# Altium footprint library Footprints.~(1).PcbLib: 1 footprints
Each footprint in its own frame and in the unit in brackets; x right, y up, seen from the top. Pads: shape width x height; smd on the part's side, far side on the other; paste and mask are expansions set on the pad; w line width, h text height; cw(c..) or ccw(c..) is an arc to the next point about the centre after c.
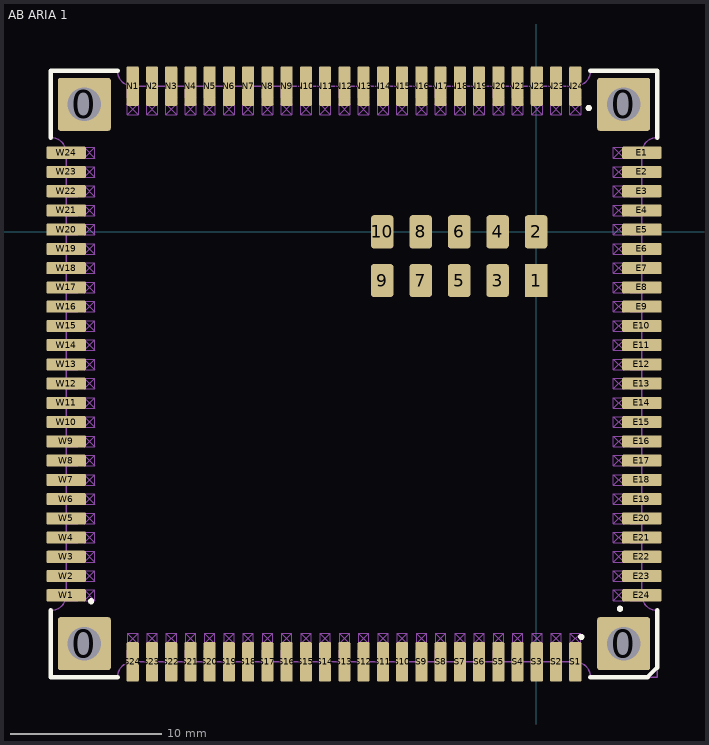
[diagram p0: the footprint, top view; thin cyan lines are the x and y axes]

## AB ARIA 1 [mm]
pads (110):
  rrect10% 3.5x3.5 hole 2.2 mask+0.2: 0(-29.82,-27.18) 0(-29.82,8.42) 0(5.78,-27.18) 0(5.78,8.42)
  rect 1.5x2.2 smd paste-0.1: 1(0,-3.21)
  rrect30% 1.5x2.2 smd paste-0.1: 2(0,0) 3(-2.54,-3.21) 4(-2.54,0) 5(-5.08,-3.21) 6(-5.08,0) 7(-7.62,-3.21) 8(-7.62,0) 9(-10.16,-3.21) 10(-10.16,0)
  rrect20% 2.6x0.8 smd paste+0.05: E1(6.98,5.225) E2(6.98,3.955) E3(6.98,2.685) E4(6.98,1.415) E5(6.98,0.145) E6(6.98,-1.125) E7(6.98,-2.395) E8(6.98,-3.665) E9(6.98,-4.935) E10(6.98,-6.205) E11(6.98,-7.475) E12(6.98,-8.745) E13(6.98,-10.015) E14(6.98,-11.285) E15(6.98,-12.555) E16(6.98,-13.825) E17(6.98,-15.095) E18(6.98,-16.365) E19(6.98,-17.635) E20(6.98,-18.905) E21(6.98,-20.175) E22(6.98,-21.445) E23(6.98,-22.715) E24(6.98,-23.985) W1(-31.02,-23.985) W2(-31.02,-22.715) W3(-31.02,-21.445) W4(-31.02,-20.175) W5(-31.02,-18.905) W6(-31.02,-17.635) W7(-31.02,-16.365) W8(-31.02,-15.095) W9(-31.02,-13.825) W10(-31.02,-12.555) W11(-31.02,-11.285) W12(-31.02,-10.015) W13(-31.02,-8.745) W14(-31.02,-7.475) W15(-31.02,-6.205) W16(-31.02,-4.935) W17(-31.02,-3.665) W18(-31.02,-2.395) W19(-31.02,-1.125) W20(-31.02,0.145) W21(-31.02,1.415) W22(-31.02,2.685) W23(-31.02,3.955) W24(-31.02,5.225)
  rrect20% 0.8x2.6 smd paste+0.05: N1(-26.625,9.62) N2(-25.355,9.62) N3(-24.085,9.62) N4(-22.815,9.62) N5(-21.545,9.62) N6(-20.275,9.62) N7(-19.005,9.62) N8(-17.735,9.62) N9(-16.465,9.62) N10(-15.195,9.62) N11(-13.925,9.62) N12(-12.655,9.62) N13(-11.385,9.62) N14(-10.115,9.62) N15(-8.845,9.62) N16(-7.575,9.62) N17(-6.305,9.62) N18(-5.035,9.62) N19(-3.765,9.62) N20(-2.495,9.62) N21(-1.225,9.62) N22(0.045,9.62) N23(1.315,9.62) N24(2.585,9.62) S1(2.585,-28.38) S2(1.315,-28.38) S3(0.045,-28.38) S4(-1.225,-28.38) S5(-2.495,-28.38) S6(-3.765,-28.38) S7(-5.035,-28.38) S8(-6.305,-28.38) S9(-7.575,-28.38) S10(-8.845,-28.38) S11(-10.115,-28.38) S12(-11.385,-28.38) S13(-12.655,-28.38) S14(-13.925,-28.38) S15(-15.195,-28.38) S16(-16.465,-28.38) S17(-17.735,-28.38) S18(-19.005,-28.38) S19(-20.275,-28.38) S20(-21.545,-28.38) S21(-22.815,-28.38) S22(-24.085,-28.38) S23(-25.355,-28.38) S24(-26.625,-28.38)
Top Overlay:
  circle w0.254: c2.98,-26.73 r0.075
  circle w0.254: c-29.37,-24.38 r0.075
  circle w0.254: c3.472,8.174 r0.075
  circle w0.254: c5.534,-24.872 r0.075
  lines w0.3: -32.02,-24.985 -32.02,-29.38 ; -32.02,6.225 -32.02,10.62 -27.625,10.62 ; -27.625,-29.38 -32.02,-29.38 ; 3.585,-29.38 7.355,-29.38 7.98,-28.755 7.98,-24.985 ; 3.585,10.62 7.98,10.62 ; 7.98,6.225 7.98,10.62 ; -32.02,-29.38 -32.02,-29.38 ; -27.625,10.62 -27.625,10.62 ; 7.98,10.62 7.98,10.62
Top Paste:
  lines w0.8: -32.77,-23.99 -32.47,-23.99 ; -32.77,-22.72 -32.47,-22.72 ; -32.77,-21.45 -32.47,-21.45 ; -32.77,-20.18 -32.47,-20.18 ; -32.77,-18.91 -32.47,-18.91 ; -32.77,-17.64 -32.47,-17.64 ; -32.77,-16.37 -32.47,-16.37 ; -32.77,-15.1 -32.47,-15.1 ; -32.77,-13.83 -32.47,-13.83 ; -32.77,-12.56 -32.47,-12.56 ; -32.77,-11.29 -32.47,-11.29 ; -32.77,-10.02 -32.47,-10.02 ; -32.77,-8.75 -32.47,-8.75 ; -32.77,-7.48 -32.47,-7.48 ; -32.77,-6.21 -32.47,-6.21 ; -32.77,-4.94 -32.47,-4.94 ; -32.77,-3.67 -32.47,-3.67 ; -32.77,-2.4 -32.47,-2.4 ; -32.77,-1.13 -32.47,-1.13 ; -32.77,0.14 -32.47,0.14 ; -32.77,1.41 -32.47,1.41 ; -32.77,2.68 -32.47,2.68 ; -32.77,3.95 -32.47,3.95 ; -32.77,5.22 -32.47,5.22 ; -26.63,11.07 -26.63,11.37 ; -26.62,-30.13 -26.62,-29.83 ; -25.36,11.07 -25.36,11.37 ; -25.35,-30.13 -25.35,-29.83 ; -24.09,11.07 -24.09,11.37 ; -24.08,-30.13 -24.08,-29.83 ; -22.82,11.07 -22.82,11.37 ; -22.81,-30.13 -22.81,-29.83 ; -21.55,11.07 -21.55,11.37 ; -21.54,-30.13 -21.54,-29.83 ; -20.28,11.07 -20.28,11.37 ; -20.27,-30.13 -20.27,-29.83 ; -19.01,11.07 -19.01,11.37 ; -19,-30.13 -19,-29.83 ; -17.74,11.07 -17.74,11.37 ; -17.73,-30.13 -17.73,-29.83 ; -16.47,11.07 -16.47,11.37 ; -16.46,-30.13 -16.46,-29.83 ; -15.2,11.07 -15.2,11.37 ; -15.19,-30.13 -15.19,-29.83 ; -13.93,11.07 -13.93,11.37 ; -13.92,-30.13 -13.92,-29.83 ; -12.66,11.07 -12.66,11.37 ; -12.65,-30.13 -12.65,-29.83 ; -11.39,11.07 -11.39,11.37 ; -11.38,-30.13 -11.38,-29.83 ; -10.12,11.07 -10.12,11.37 ; -10.11,-30.13 -10.11,-29.83 ; -8.85,11.07 -8.85,11.37 ; -8.84,-30.13 -8.84,-29.83 ; -7.58,11.07 -7.58,11.37 ; -7.57,-30.13 -7.57,-29.83 ; -6.31,11.07 -6.31,11.37 ; -6.3,-30.13 -6.3,-29.83 ; -5.04,11.07 -5.04,11.37 ; -5.03,-30.13 -5.03,-29.83 ; -3.77,11.07 -3.77,11.37 ; -3.76,-30.13 -3.76,-29.83 ; -2.5,11.07 -2.5,11.37 ; -2.49,-30.13 -2.49,-29.83 ; -1.23,11.07 -1.23,11.37 ; -1.22,-30.13 -1.22,-29.83 ; 0.04,11.07 0.04,11.37 ; 0.05,-30.13 0.05,-29.83 ; 1.31,11.07 1.31,11.37 ; 1.32,-30.13 1.32,-29.83 ; 2.58,11.07 2.58,11.37 ; 2.59,-30.13 2.59,-29.83 ; 8.43,-23.98 8.73,-23.98 ; 8.43,-22.71 8.73,-22.71 ; 8.43,-21.44 8.73,-21.44 ; 8.43,-20.17 8.73,-20.17 ; 8.43,-18.9 8.73,-18.9 ; 8.43,-17.63 8.73,-17.63 ; 8.43,-16.36 8.73,-16.36 ; 8.43,-15.09 8.73,-15.09 ; 8.43,-13.82 8.73,-13.82 ; 8.43,-12.55 8.73,-12.55 ; 8.43,-11.28 8.73,-11.28 ; 8.43,-10.01 8.73,-10.01 ; 8.43,-8.74 8.73,-8.74 ; 8.43,-7.47 8.73,-7.47 ; 8.43,-6.2 8.73,-6.2 ; 8.43,-4.93 8.73,-4.93 ; 8.43,-3.66 8.73,-3.66 ; 8.43,-2.39 8.73,-2.39 ; 8.43,-1.12 8.73,-1.12 ; 8.43,0.15 8.73,0.15 ; 8.43,1.42 8.73,1.42 ; 8.43,2.69 8.73,2.69 ; 8.43,3.96 8.73,3.96 ; 8.43,5.23 8.73,5.23
Bottom Solder:
  region: -1.866,-2.181 -3.23,-2.181 -3.23,-4.219 -1.866,-4.219
  region: -1.857,1.017 -3.221,1.017 -3.221,-1.021 -1.857,-1.021
  region: 0.68,1.017 -0.684,1.017 -0.684,-1.021 0.68,-1.021
Mechanical 13:
  lines w0.1: 2.585,-28.38 cw(c2.585,-29.38) 3.585,-29.38 7.98,-29.38 7.98,-24.985 cw(c7.98,-23.985) 6.98,-23.985 6.98,5.225 cw(c7.98,5.225) 7.98,6.225 7.98,10.62 3.585,10.62 cw(c2.585,10.62) 2.585,9.62 -26.625,9.62 cw(c-26.625,10.62) -27.625,10.62 -32.02,10.62 -32.02,6.225 cw(c-32.02,5.225) -31.02,5.225 -31.02,-23.985 cw(c-32.02,-23.985) -32.02,-24.985 -32.02,-29.38 -27.625,-29.38 cw(c-26.625,-29.38) -26.625,-28.38 2.635,-28.38
Mechanical 15:
  drawing of 1308 lines, arcs and shapes, not listed
3D body: height 2.75, standoff 0.01, extent -32.075,-29.435 8.034,10.674
3D body: height 0.1, standoff 0.01, extent -10.81,-4.21 -9.51,-2.21
3D body: height 0.1, standoff 0.01, extent -8.27,-4.21 -6.97,-2.21
3D body: height 0.1, standoff 0.01, extent -5.73,-4.21 -4.43,-2.21
3D body: height 0.1, standoff 0.01, extent -3.19,-4.21 -1.89,-2.21
3D body: height 0.1, standoff 0.01, extent -0.65,-4.21 0.65,-2.21
3D body: height 0.1, standoff 0.01, extent -10.81,-1 -9.51,1
3D body: height 0.1, standoff 0.01, extent -8.27,-1 -6.97,1
3D body: height 0.1, standoff 0.01, extent -5.73,-1 -4.43,1
3D body: height 0.1, standoff 0.01, extent -3.19,-1 -1.89,1
3D body: height 0.1, standoff 0.01, extent -0.65,-1 0.65,1
3D body: height 1.51, standoff 0.01, extent -12.66,4.32 -11.3,5.89
3D body: height 1.51, standoff 0.01, extent -13.619,6.619 -10.42,8.22
3D body: height 1.51, standoff 1.4, extent 5.8,4.875 7.03,5.575
3D body: height 0.1, standoff 0.01, extent 5.1,4.875 5.8,5.575
3D body: height 1.4, standoff 0.01, extent 6.21,4.875 7.03,5.575
3D body: height 1.4, standoff 0.01, extent 6.21,3.605 7.03,4.305
3D body: height 0.1, standoff 0.01, extent 5.1,3.605 5.8,4.305
3D body: height 1.51, standoff 1.4, extent 6.21,3.605 7.03,4.305
3D body: height 1.4, standoff 0.01, extent 6.21,2.335 7.03,3.035
3D body: height 0.1, standoff 0.01, extent 5.1,2.335 5.8,3.035
3D body: height 1.51, standoff 1.4, extent 6.21,2.335 7.03,3.035
3D body: height 1.4, standoff 0.01, extent 6.21,1.065 7.03,1.765
3D body: height 0.1, standoff 0.01, extent 5.1,1.065 5.8,1.765
3D body: height 1.51, standoff 1.4, extent 6.21,1.065 7.03,1.765
3D body: height 1.4, standoff 0.01, extent 6.21,-0.205 7.03,0.495
3D body: height 0.1, standoff 0.01, extent 5.1,-0.205 5.8,0.495
3D body: height 1.51, standoff 1.4, extent 6.21,-0.205 7.03,0.495
3D body: height 1.4, standoff 0.01, extent 6.21,-1.475 7.03,-0.775
3D body: height 0.1, standoff 0.01, extent 5.1,-1.475 5.8,-0.775
3D body: height 1.51, standoff 1.4, extent 6.21,-1.475 7.03,-0.775
3D body: height 1.4, standoff 0.01, extent 6.21,-2.745 7.03,-2.045
3D body: height 0.1, standoff 0.01, extent 5.1,-2.745 5.8,-2.045
3D body: height 1.51, standoff 1.4, extent 6.21,-2.745 7.03,-2.045
3D body: height 1.4, standoff 0.01, extent 6.21,-4.015 7.03,-3.315
3D body: height 0.1, standoff 0.01, extent 5.1,-4.015 5.8,-3.315
3D body: height 1.51, standoff 1.4, extent 6.21,-4.015 7.03,-3.315
3D body: height 1.4, standoff 0.01, extent 6.21,-5.285 7.03,-4.585
3D body: height 0.1, standoff 0.01, extent 5.1,-5.285 5.8,-4.585
3D body: height 1.51, standoff 1.4, extent 6.21,-5.285 7.03,-4.585
3D body: height 1.4, standoff 0.01, extent 6.21,-6.555 7.03,-5.855
3D body: height 0.1, standoff 0.01, extent 5.1,-6.555 5.8,-5.855
3D body: height 1.51, standoff 1.4, extent 6.21,-6.555 7.03,-5.855
3D body: height 1.4, standoff 0.01, extent 6.21,-7.825 7.03,-7.125
3D body: height 0.1, standoff 0.01, extent 5.1,-7.825 5.8,-7.125
3D body: height 1.51, standoff 1.4, extent 6.21,-7.825 7.03,-7.125
3D body: height 1.4, standoff 0.01, extent 6.21,-9.095 7.03,-8.395
3D body: height 0.1, standoff 0.01, extent 5.1,-9.095 5.8,-8.395
3D body: height 1.51, standoff 1.4, extent 6.21,-9.095 7.03,-8.395
3D body: height 1.4, standoff 0.01, extent 6.21,-10.365 7.03,-9.665
3D body: height 0.1, standoff 0.01, extent 5.1,-10.365 5.8,-9.665
3D body: height 1.51, standoff 1.4, extent 6.21,-10.365 7.03,-9.665
3D body: height 1.4, standoff 0.01, extent 6.21,-11.635 7.03,-10.935
3D body: height 0.1, standoff 0.01, extent 5.1,-11.635 5.8,-10.935
3D body: height 1.51, standoff 1.4, extent 6.21,-11.635 7.03,-10.935
3D body: height 1.4, standoff 0.01, extent 6.21,-12.905 7.03,-12.205
3D body: height 0.1, standoff 0.01, extent 5.1,-12.905 5.8,-12.205
3D body: height 1.51, standoff 1.4, extent 6.21,-12.905 7.03,-12.205
3D body: height 1.4, standoff 0.01, extent 6.21,-14.175 7.03,-13.475
3D body: height 0.1, standoff 0.01, extent 5.1,-14.175 5.8,-13.475
3D body: height 1.51, standoff 1.4, extent 6.21,-14.175 7.03,-13.475
3D body: height 1.4, standoff 0.01, extent 6.21,-15.445 7.03,-14.745
3D body: height 0.1, standoff 0.01, extent 5.1,-15.445 5.8,-14.745
3D body: height 1.51, standoff 1.4, extent 6.21,-15.445 7.03,-14.745
3D body: height 1.4, standoff 0.01, extent 6.21,-16.715 7.03,-16.015
3D body: height 0.1, standoff 0.01, extent 5.1,-16.715 5.8,-16.015
3D body: height 1.51, standoff 1.4, extent 6.21,-16.715 7.03,-16.015
3D body: height 1.4, standoff 0.01, extent 6.21,-17.985 7.03,-17.285
3D body: height 0.1, standoff 0.01, extent 5.1,-17.985 5.8,-17.285
3D body: height 1.51, standoff 1.4, extent 6.21,-17.985 7.03,-17.285
3D body: height 1.4, standoff 0.01, extent 6.21,-19.255 7.03,-18.555
3D body: height 0.1, standoff 0.01, extent 5.1,-19.255 5.8,-18.555
3D body: height 1.51, standoff 1.4, extent 6.21,-19.255 7.03,-18.555
3D body: height 1.4, standoff 0.01, extent 6.21,-20.525 7.03,-19.825
3D body: height 0.1, standoff 0.01, extent 5.1,-20.525 5.8,-19.825
3D body: height 1.51, standoff 1.4, extent 6.21,-20.525 7.03,-19.825
3D body: height 1.4, standoff 0.01, extent 6.21,-21.795 7.03,-21.095
3D body: height 0.1, standoff 0.01, extent 5.1,-21.795 5.8,-21.095
3D body: height 1.51, standoff 1.4, extent 6.21,-21.795 7.03,-21.095
3D body: height 1.4, standoff 0.01, extent 6.21,-23.065 7.03,-22.365
3D body: height 0.1, standoff 0.01, extent 5.1,-23.065 5.8,-22.365
3D body: height 1.51, standoff 1.4, extent 6.21,-23.065 7.03,-22.365
3D body: height 1.4, standoff 0.01, extent 6.21,-24.335 7.03,-23.635
3D body: height 0.1, standoff 0.01, extent 5.1,-24.335 5.8,-23.635
3D body: height 1.51, standoff 1.4, extent 6.21,-24.335 7.03,-23.635
3D body: height 1.4, standoff 0.01, extent 2.235,-28.43 2.935,-27.61
3D body: height 0.1, standoff 0.01, extent 2.235,-27.2 2.935,-26.5
3D body: height 1.51, standoff 1.4, extent 2.235,-28.43 2.935,-27.2
3D body: height 1.4, standoff 0.01, extent 0.965,-28.43 1.665,-27.61
3D body: height 0.1, standoff 0.01, extent 0.965,-27.2 1.665,-26.5
3D body: height 1.51, standoff 1.4, extent 0.965,-28.43 1.665,-27.61
3D body: height 1.4, standoff 0.01, extent -0.305,-28.43 0.395,-27.61
3D body: height 0.1, standoff 0.01, extent -0.305,-27.2 0.395,-26.5
3D body: height 1.51, standoff 1.4, extent -0.305,-28.43 0.395,-27.61
3D body: height 1.4, standoff 0.01, extent -1.575,-28.43 -0.875,-27.61
3D body: height 0.1, standoff 0.01, extent -1.575,-27.2 -0.875,-26.5
3D body: height 1.51, standoff 1.4, extent -1.575,-28.43 -0.875,-27.61
3D body: height 1.4, standoff 0.01, extent -2.845,-28.43 -2.145,-27.61
3D body: height 0.1, standoff 0.01, extent -2.845,-27.2 -2.145,-26.5
3D body: height 1.51, standoff 1.4, extent -2.845,-28.43 -2.145,-27.61
3D body: height 1.4, standoff 0.01, extent -4.115,-28.43 -3.415,-27.61
3D body: height 0.1, standoff 0.01, extent -4.115,-27.2 -3.415,-26.5
3D body: height 1.51, standoff 1.4, extent -4.115,-28.43 -3.415,-27.61
3D body: height 1.4, standoff 0.01, extent -5.385,-28.43 -4.685,-27.61
3D body: height 0.1, standoff 0.01, extent -5.385,-27.2 -4.685,-26.5
3D body: height 1.51, standoff 1.4, extent -5.385,-28.43 -4.685,-27.61
3D body: height 1.4, standoff 0.01, extent -6.655,-28.43 -5.955,-27.61
3D body: height 0.1, standoff 0.01, extent -6.655,-27.2 -5.955,-26.5
3D body: height 1.51, standoff 1.4, extent -6.655,-28.43 -5.955,-27.61
3D body: height 1.4, standoff 0.01, extent -7.925,-28.43 -7.225,-27.61
3D body: height 0.1, standoff 0.01, extent -7.925,-27.2 -7.225,-26.5
3D body: height 1.51, standoff 1.4, extent -7.925,-28.43 -7.225,-27.61
3D body: height 1.4, standoff 0.01, extent -9.195,-28.43 -8.495,-27.61
3D body: height 0.1, standoff 0.01, extent -9.195,-27.2 -8.495,-26.5
3D body: height 1.51, standoff 1.4, extent -9.195,-28.43 -8.495,-27.61
3D body: height 1.4, standoff 0.01, extent -10.465,-28.43 -9.765,-27.61
3D body: height 0.1, standoff 0.01, extent -10.465,-27.2 -9.765,-26.5
3D body: height 1.51, standoff 1.4, extent -10.465,-28.43 -9.765,-27.61
3D body: height 1.4, standoff 0.01, extent -11.735,-28.43 -11.035,-27.61
3D body: height 0.1, standoff 0.01, extent -11.735,-27.2 -11.035,-26.5
3D body: height 1.51, standoff 1.4, extent -11.735,-28.43 -11.035,-27.61
3D body: height 1.4, standoff 0.01, extent -13.005,-28.43 -12.305,-27.61
3D body: height 0.1, standoff 0.01, extent -13.005,-27.2 -12.305,-26.5
3D body: height 1.51, standoff 1.4, extent -13.005,-28.43 -12.305,-27.61
3D body: height 1.4, standoff 0.01, extent -14.275,-28.43 -13.575,-27.61
3D body: height 0.1, standoff 0.01, extent -14.275,-27.2 -13.575,-26.5
3D body: height 1.51, standoff 1.4, extent -14.275,-28.43 -13.575,-27.61
3D body: height 1.4, standoff 0.01, extent -15.545,-28.43 -14.845,-27.61
3D body: height 0.1, standoff 0.01, extent -15.545,-27.2 -14.845,-26.5
3D body: height 1.51, standoff 1.4, extent -15.545,-28.43 -14.845,-27.61
3D body: height 1.4, standoff 0.01, extent -16.815,-28.43 -16.115,-27.61
3D body: height 0.1, standoff 0.01, extent -16.815,-27.2 -16.115,-26.5
3D body: height 1.51, standoff 1.4, extent -16.815,-28.43 -16.115,-27.61
3D body: height 1.4, standoff 0.01, extent -18.085,-28.43 -17.385,-27.61
3D body: height 0.1, standoff 0.01, extent -18.085,-27.2 -17.385,-26.5
3D body: height 1.51, standoff 1.4, extent -18.085,-28.43 -17.385,-27.61
3D body: height 1.4, standoff 0.01, extent -19.355,-28.43 -18.655,-27.61
3D body: height 0.1, standoff 0.01, extent -19.355,-27.2 -18.655,-26.5
3D body: height 1.51, standoff 1.4, extent -19.355,-28.43 -18.655,-27.61
3D body: height 1.4, standoff 0.01, extent -20.625,-28.43 -19.925,-27.61
3D body: height 0.1, standoff 0.01, extent -20.625,-27.2 -19.925,-26.5
3D body: height 1.51, standoff 1.4, extent -20.625,-28.43 -19.925,-27.61
3D body: height 1.4, standoff 0.01, extent -21.895,-28.43 -21.195,-27.61
3D body: height 0.1, standoff 0.01, extent -21.895,-27.2 -21.195,-26.5
3D body: height 1.51, standoff 1.4, extent -21.895,-28.43 -21.195,-27.61
3D body: height 1.4, standoff 0.01, extent -23.165,-28.43 -22.465,-27.61
3D body: height 0.1, standoff 0.01, extent -23.165,-27.2 -22.465,-26.5
3D body: height 1.51, standoff 1.4, extent -23.165,-28.43 -22.465,-27.61
3D body: height 1.4, standoff 0.01, extent -24.435,-28.43 -23.735,-27.61
3D body: height 0.1, standoff 0.01, extent -24.435,-27.2 -23.735,-26.5
3D body: height 1.51, standoff 1.4, extent -24.435,-28.43 -23.735,-27.61
3D body: height 1.4, standoff 0.01, extent -25.705,-28.43 -25.005,-27.61
3D body: height 0.1, standoff 0.01, extent -25.705,-27.2 -25.005,-26.5
3D body: height 1.51, standoff 1.4, extent -25.705,-28.43 -25.005,-27.61
3D body: height 1.4, standoff 0.01, extent -26.975,-28.43 -26.275,-27.61
3D body: height 0.1, standoff 0.01, extent -26.975,-27.2 -26.275,-26.5
3D body: height 1.51, standoff 1.4, extent -26.975,-28.43 -26.275,-27.61
3D body: height 1.4, standoff 0.01, extent -31.07,-24.335 -30.25,-23.635
3D body: height 0.1, standoff 0.01, extent -29.84,-24.335 -29.14,-23.635
3D body: height 1.51, standoff 1.4, extent -31.07,-24.335 -29.84,-23.635
3D body: height 1.4, standoff 0.01, extent -31.07,-23.065 -30.25,-22.365
3D body: height 0.1, standoff 0.01, extent -29.84,-23.065 -29.14,-22.365
3D body: height 1.51, standoff 1.4, extent -31.07,-23.065 -30.25,-22.365
3D body: height 1.4, standoff 0.01, extent -31.07,-21.795 -30.25,-21.095
3D body: height 0.1, standoff 0.01, extent -29.84,-21.795 -29.14,-21.095
3D body: height 1.51, standoff 1.4, extent -31.07,-21.795 -30.25,-21.095
3D body: height 1.4, standoff 0.01, extent -31.07,-20.525 -30.25,-19.825
3D body: height 0.1, standoff 0.01, extent -29.84,-20.525 -29.14,-19.825
3D body: height 1.51, standoff 1.4, extent -31.07,-20.525 -30.25,-19.825
3D body: height 1.4, standoff 0.01, extent -31.07,-19.255 -30.25,-18.555
3D body: height 0.1, standoff 0.01, extent -29.84,-19.255 -29.14,-18.555
3D body: height 1.51, standoff 1.4, extent -31.07,-19.255 -30.25,-18.555
3D body: height 1.4, standoff 0.01, extent -31.07,-17.985 -30.25,-17.285
3D body: height 0.1, standoff 0.01, extent -29.84,-17.985 -29.14,-17.285
3D body: height 1.51, standoff 1.4, extent -31.07,-17.985 -30.25,-17.285
3D body: height 1.4, standoff 0.01, extent -31.07,-16.715 -30.25,-16.015
3D body: height 0.1, standoff 0.01, extent -29.84,-16.715 -29.14,-16.015
3D body: height 1.51, standoff 1.4, extent -31.07,-16.715 -30.25,-16.015
3D body: height 1.4, standoff 0.01, extent -31.07,-15.445 -30.25,-14.745
3D body: height 0.1, standoff 0.01, extent -29.84,-15.445 -29.14,-14.745
3D body: height 1.51, standoff 1.4, extent -31.07,-15.445 -30.25,-14.745
3D body: height 1.4, standoff 0.01, extent -31.07,-14.175 -30.25,-13.475
3D body: height 0.1, standoff 0.01, extent -29.84,-14.175 -29.14,-13.475
3D body: height 1.51, standoff 1.4, extent -31.07,-14.175 -30.25,-13.475
3D body: height 1.4, standoff 0.01, extent -31.07,-12.905 -30.25,-12.205
3D body: height 0.1, standoff 0.01, extent -29.84,-12.905 -29.14,-12.205
3D body: height 1.51, standoff 1.4, extent -31.07,-12.905 -30.25,-12.205
3D body: height 1.4, standoff 0.01, extent -31.07,-11.635 -30.25,-10.935
3D body: height 0.1, standoff 0.01, extent -29.84,-11.635 -29.14,-10.935
3D body: height 1.51, standoff 1.4, extent -31.07,-11.635 -30.25,-10.935
3D body: height 1.4, standoff 0.01, extent -31.07,-10.365 -30.25,-9.665
3D body: height 0.1, standoff 0.01, extent -29.84,-10.365 -29.14,-9.665
3D body: height 1.51, standoff 1.4, extent -31.07,-10.365 -30.25,-9.665
3D body: height 1.4, standoff 0.01, extent -31.07,-9.095 -30.25,-8.395
3D body: height 0.1, standoff 0.01, extent -29.84,-9.095 -29.14,-8.395
3D body: height 1.51, standoff 1.4, extent -31.07,-9.095 -30.25,-8.395
3D body: height 1.4, standoff 0.01, extent -31.07,-7.825 -30.25,-7.125
3D body: height 0.1, standoff 0.01, extent -29.84,-7.825 -29.14,-7.125
3D body: height 1.51, standoff 1.4, extent -31.07,-7.825 -30.25,-7.125
3D body: height 1.4, standoff 0.01, extent -31.07,-6.555 -30.25,-5.855
3D body: height 0.1, standoff 0.01, extent -29.84,-6.555 -29.14,-5.855
3D body: height 1.51, standoff 1.4, extent -31.07,-6.555 -30.25,-5.855
3D body: height 1.4, standoff 0.01, extent -31.07,-5.285 -30.25,-4.585
3D body: height 0.1, standoff 0.01, extent -29.84,-5.285 -29.14,-4.585
3D body: height 1.51, standoff 1.4, extent -31.07,-5.285 -30.25,-4.585
3D body: height 1.4, standoff 0.01, extent -31.07,-4.015 -30.25,-3.315
3D body: height 0.1, standoff 0.01, extent -29.84,-4.015 -29.14,-3.315
3D body: height 1.51, standoff 1.4, extent -31.07,-4.015 -30.25,-3.315
3D body: height 1.4, standoff 0.01, extent -31.07,-2.745 -30.25,-2.045
3D body: height 0.1, standoff 0.01, extent -29.84,-2.745 -29.14,-2.045
3D body: height 1.51, standoff 1.4, extent -31.07,-2.745 -30.25,-2.045
3D body: height 1.4, standoff 0.01, extent -31.07,-1.475 -30.25,-0.775
3D body: height 0.1, standoff 0.01, extent -29.84,-1.475 -29.14,-0.775
3D body: height 1.51, standoff 1.4, extent -31.07,-1.475 -30.25,-0.775
3D body: height 1.4, standoff 0.01, extent -31.07,-0.205 -30.25,0.495
3D body: height 0.1, standoff 0.01, extent -29.84,-0.205 -29.14,0.495
3D body: height 1.51, standoff 1.4, extent -31.07,-0.205 -30.25,0.495
3D body: height 1.4, standoff 0.01, extent -31.07,1.065 -30.25,1.765
3D body: height 0.1, standoff 0.01, extent -29.84,1.065 -29.14,1.765
3D body: height 1.51, standoff 1.4, extent -31.07,1.065 -30.25,1.765
3D body: height 1.4, standoff 0.01, extent -31.07,2.335 -30.25,3.035
3D body: height 0.1, standoff 0.01, extent -29.84,2.335 -29.14,3.035
3D body: height 1.51, standoff 1.4, extent -31.07,2.335 -30.25,3.035
3D body: height 1.4, standoff 0.01, extent -31.07,3.605 -30.25,4.305
3D body: height 0.1, standoff 0.01, extent -29.84,3.605 -29.14,4.305
3D body: height 1.51, standoff 1.4, extent -31.07,3.605 -30.25,4.305
3D body: height 1.4, standoff 0.01, extent -31.07,4.875 -30.25,5.575
3D body: height 0.1, standoff 0.01, extent -29.84,4.875 -29.14,5.575
3D body: height 1.51, standoff 1.4, extent -31.07,4.875 -30.25,5.575
3D body: height 1.4, standoff 0.01, extent -26.975,8.85 -26.275,9.67
3D body: height 0.1, standoff 0.01, extent -26.975,7.74 -26.275,8.44
3D body: height 1.51, standoff 1.4, extent -26.975,8.44 -26.275,9.67
3D body: height 1.4, standoff 0.01, extent -25.705,8.85 -25.005,9.67
3D body: height 0.1, standoff 0.01, extent -25.705,7.74 -25.005,8.44
3D body: height 1.51, standoff 1.4, extent -25.705,8.85 -25.005,9.67
3D body: height 1.4, standoff 0.01, extent -24.435,8.85 -23.735,9.67
3D body: height 0.1, standoff 0.01, extent -24.435,7.74 -23.735,8.44
3D body: height 1.51, standoff 1.4, extent -24.435,8.85 -23.735,9.67
3D body: height 1.4, standoff 0.01, extent -23.165,8.85 -22.465,9.67
3D body: height 0.1, standoff 0.01, extent -23.165,7.74 -22.465,8.44
3D body: height 1.51, standoff 1.4, extent -23.165,8.85 -22.465,9.67
3D body: height 1.4, standoff 0.01, extent -21.895,8.85 -21.195,9.67
3D body: height 0.1, standoff 0.01, extent -21.895,7.74 -21.195,8.44
3D body: height 1.51, standoff 1.4, extent -21.895,8.85 -21.195,9.67
3D body: height 1.4, standoff 0.01, extent -20.625,8.85 -19.925,9.67
3D body: height 0.1, standoff 0.01, extent -20.625,7.74 -19.925,8.44
3D body: height 1.51, standoff 1.4, extent -20.625,8.85 -19.925,9.67
3D body: height 1.4, standoff 0.01, extent -19.355,8.85 -18.655,9.67
3D body: height 0.1, standoff 0.01, extent -19.355,7.74 -18.655,8.44
3D body: height 1.51, standoff 1.4, extent -19.355,8.85 -18.655,9.67
3D body: height 1.4, standoff 0.01, extent -18.085,8.85 -17.385,9.67
3D body: height 0.1, standoff 0.01, extent -18.085,7.74 -17.385,8.44
3D body: height 1.51, standoff 1.4, extent -18.085,8.85 -17.385,9.67
3D body: height 1.51, standoff 1.4, extent -16.815,8.85 -16.115,9.67
3D body: height 0.1, standoff 0.01, extent -16.815,7.74 -16.115,8.44
3D body: height 1.4, standoff 0.01, extent -16.815,8.85 -16.115,9.67
3D body: height 1.51, standoff 1.4, extent -15.545,8.85 -14.845,9.67
3D body: height 0.1, standoff 0.01, extent -15.545,7.74 -14.845,8.44
3D body: height 1.4, standoff 0.01, extent -15.545,8.85 -14.845,9.67
3D body: height 1.51, standoff 1.4, extent -14.275,8.85 -13.575,9.67
3D body: height 0.1, standoff 0.01, extent -14.275,7.74 -13.575,8.44
3D body: height 1.4, standoff 0.01, extent -14.275,8.85 -13.575,9.67
3D body: height 1.51, standoff 1.4, extent -13.005,8.85 -12.305,9.67
3D body: height 0.1, standoff 0.01, extent -13.005,7.74 -12.305,8.44
3D body: height 1.4, standoff 0.01, extent -13.005,8.85 -12.305,9.67
3D body: height 1.51, standoff 1.4, extent -11.735,8.85 -11.035,9.67
3D body: height 0.1, standoff 0.01, extent -11.735,7.74 -11.035,8.44
3D body: height 1.4, standoff 0.01, extent -11.735,8.85 -11.035,9.67
3D body: height 1.51, standoff 1.4, extent -10.465,8.85 -9.765,9.67
3D body: height 0.1, standoff 0.01, extent -10.465,7.74 -9.765,8.44
3D body: height 1.4, standoff 0.01, extent -10.465,8.85 -9.765,9.67
3D body: height 1.51, standoff 1.4, extent -9.195,8.85 -8.495,9.67
3D body: height 0.1, standoff 0.01, extent -9.195,7.74 -8.495,8.44
3D body: height 1.4, standoff 0.01, extent -9.195,8.85 -8.495,9.67
3D body: height 1.51, standoff 1.4, extent -7.925,8.85 -7.225,9.67
3D body: height 0.1, standoff 0.01, extent -7.925,7.74 -7.225,8.44
3D body: height 1.4, standoff 0.01, extent -7.925,8.85 -7.225,9.67
3D body: height 1.51, standoff 1.4, extent -6.655,8.85 -5.955,9.67
3D body: height 0.1, standoff 0.01, extent -6.655,7.74 -5.955,8.44
3D body: height 1.4, standoff 0.01, extent -6.655,8.85 -5.955,9.67
3D body: height 1.51, standoff 1.4, extent -5.385,8.85 -4.685,9.67
3D body: height 0.1, standoff 0.01, extent -5.385,7.74 -4.685,8.44
3D body: height 1.4, standoff 0.01, extent -5.385,8.85 -4.685,9.67
3D body: height 1.51, standoff 1.4, extent -4.115,8.85 -3.415,9.67
3D body: height 0.1, standoff 0.01, extent -4.115,7.74 -3.415,8.44
3D body: height 1.4, standoff 0.01, extent -4.115,8.85 -3.415,9.67
3D body: height 1.51, standoff 1.4, extent 2.235,8.85 2.935,9.67
3D body: height 0.1, standoff 0.01, extent 2.235,7.74 2.935,8.44
3D body: height 1.4, standoff 0.01, extent 2.235,8.85 2.935,9.67
3D body: height 1.51, standoff 1.4, extent 0.965,8.85 1.665,9.67
3D body: height 0.1, standoff 0.01, extent 0.965,7.74 1.665,8.44
3D body: height 1.4, standoff 0.01, extent 0.965,8.85 1.665,9.67
3D body: height 1.51, standoff 1.4, extent -0.305,8.85 0.395,9.67
3D body: height 0.1, standoff 0.01, extent -0.305,7.74 0.395,8.44
3D body: height 1.4, standoff 0.01, extent -0.305,8.85 0.395,9.67
3D body: height 1.51, standoff 1.4, extent -1.575,8.85 -0.875,9.67
3D body: height 0.1, standoff 0.01, extent -1.575,7.74 -0.875,8.44
3D body: height 1.4, standoff 0.01, extent -1.575,8.85 -0.875,9.67
3D body: height 1.51, standoff 1.4, extent -2.845,8.85 -2.145,9.67
3D body: height 0.1, standoff 0.01, extent -2.845,7.74 -2.145,8.44
3D body: height 1.4, standoff 0.01, extent -2.845,8.85 -2.145,9.67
